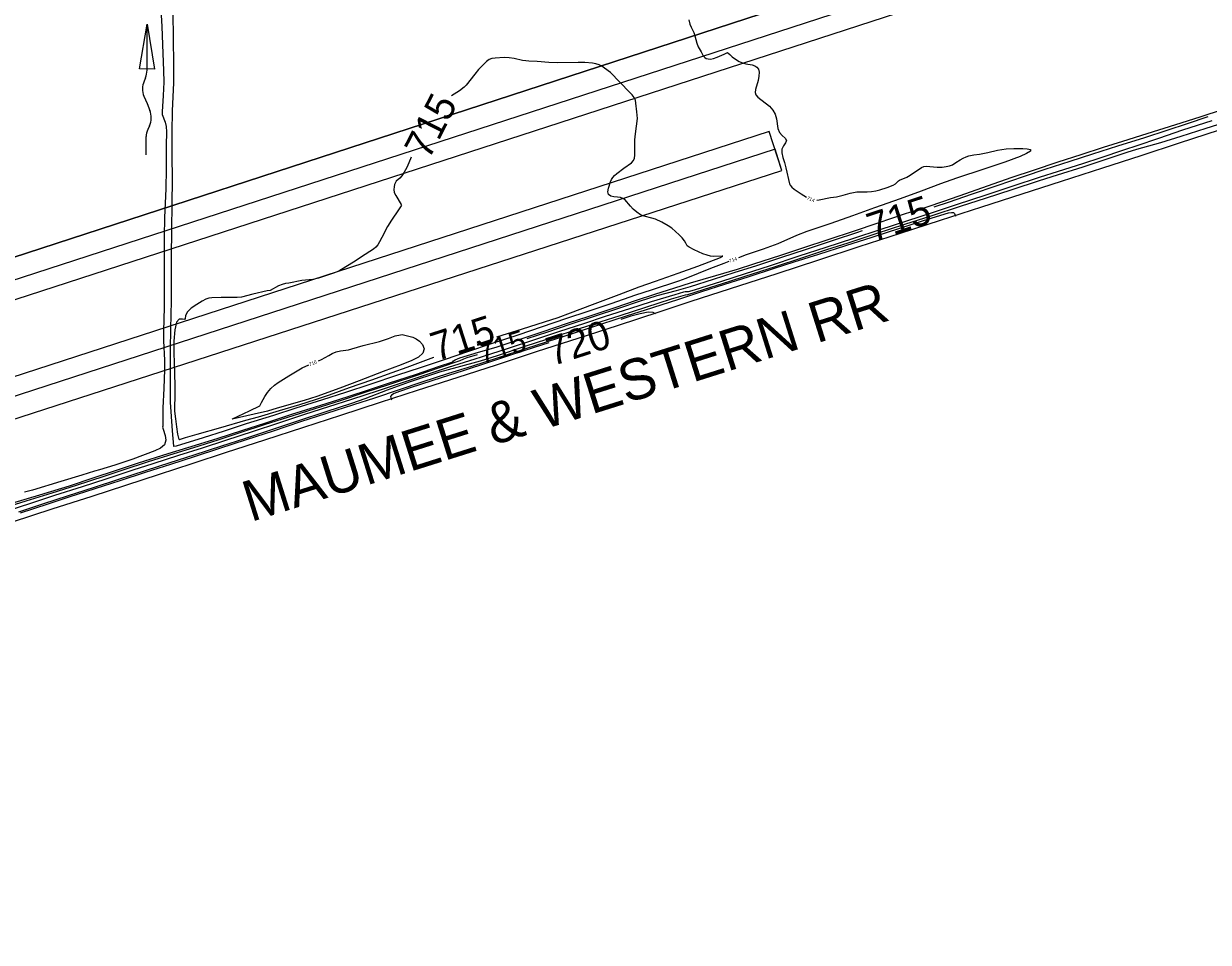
# Model space of a CAD drawing. Extents: x -468556195 to 3353078, y -306091294 to 1252632.
# Drawn here: x 1832292 to 1833652, y 533929 to 534984 of the extents above; entities that cross this region are included whole.
import ezdxf

# ---------------------------------------------------------------- set-up
doc = ezdxf.new("R2010")
doc.units = 0
for name, color, linetype in [('Default', 7, 'Continuous'), ('DT_X_Contour_Minor', 7, 'Continuous'), ('Level 14', 7, 'Continuous'), ('Level 19', 7, 'Continuous'), ('Level 31', 7, 'Continuous'), ('Level 40', 7, 'Continuous'), ('SC_Shading3', 7, 'Continuous')]:
    doc.layers.add(name, color=color, linetype=linetype)

msp = doc.modelspace()

# ---------------------------------------------------------------- linework, layer by layer
at = {"layer": 'Default'}
for points in [[(1827117.1, 533034.5), (1827123.3, 533015.5), (1834732.4, 535485.8), (1834724, 535511.6)], [(1827162.8, 532893.7), (1827168.8, 532875.3), (1833162.6, 534815.3), (1833154.9, 534839.7)]]:
    msp.add_lwpolyline(points, close=True, dxfattribs=at)
at = {"layer": 'DT_X_Contour_Minor'}
for points in [[(1833101.6, 534710.8), (1833095.9, 534708.6), (1833080.6, 534702.7), (1833052.3, 534691.2), (1833043.8, 534688.2), (1833012.6, 534677.9), (1832994.6, 534671.9), (1832966, 534662.2), (1832939.9, 534653.5), (1832915.1, 534645.1), (1832886.1, 534635.2), (1832860.4, 534626.7), (1832828.8, 534616.3), (1832801.4, 534607), (1832775.8, 534598.4), (1832747.2, 534588.7), (1832721.3, 534580.1), (1832689.2, 534569.5), (1832661.3, 534560.4), (1832635.1, 534551.9), (1832604.4, 534542.2), (1832578.6, 534534), (1832547.5, 534524.2), (1832522, 534516), (1832498.1, 534508.4), (1832466.8, 534498.8), (1832464.4, 534498.3), (1832464.2, 534498.9), (1832462.8, 534516.4), (1832460.5, 534549.3), (1832460.6, 534578.6), (1832460.4, 534602.3), (1832460.3, 534609.8), (1832460.9, 534633.5), (1832461.6, 534665.7), (1832461.7, 534691), (1832461.8, 534718.3), (1832461.9, 534744.6), (1832462.3, 534779.3), (1832462.6, 534802.6), (1832462.3, 534834.9), (1832462.3, 534859), (1832462.9, 534883.7), (1832464.1, 534915.7), (1832464.2, 534938.4), (1832464, 534965), (1832463.7, 534998.2)], [(1832449.8, 534993.3), (1832450.4, 534980.6), (1832451.6, 534949.3), (1832452.5, 534930.1), (1832452.8, 534916.4), (1832452.1, 534901.1), (1832450.9, 534882.6), (1832450.8, 534879.6), (1832454.5, 534870.5), (1832455.3, 534865.6), (1832455.7, 534859.5), (1832455.6, 534843.8), (1832455.4, 534817.2), (1832455.1, 534794.1), (1832453.7, 534761.2), (1832453.3, 534739), (1832453.2, 534712.3), (1832453.3, 534675.6), (1832453.2, 534658.4), (1832452.5, 534630.4), (1832452.5, 534619.7), (1832453.5, 534597.5), (1832453.6, 534586.7), (1832452.9, 534565), (1832451.8, 534542.8), (1832451.5, 534521.7), (1832451.3, 534520.4), (1832452, 534518.3), (1832454.4, 534511), (1832455.1, 534505.6), (1832453.6, 534500.4), (1832449, 534496.3), (1832442.5, 534493.2), (1832417.3, 534483.8), (1832396.5, 534476.8), (1832379.1, 534471.4), (1832373, 534469.9), (1832358.6, 534465.5), (1832334.6, 534458), (1832301.8, 534448.3), (1832292.9, 534445.8)], [(1833055.7, 534988), (1833056.8, 534983.3), (1833058.4, 534979.7), (1833061.6, 534973.6), (1833062.8, 534969.8), (1833065.1, 534961.2), (1833066.6, 534957.3), (1833069.8, 534951.3), (1833072.3, 534946.9), (1833074.3, 534944.7), (1833075.8, 534943.8), (1833077.9, 534943.2), (1833080.6, 534943), (1833084.2, 534943.7), (1833088.4, 534945.2), (1833096.3, 534948.8), (1833100.1, 534950.7), (1833100.6, 534950.3), (1833102.8, 534948.2), (1833105.6, 534945.7), (1833109.3, 534942.8), (1833113.4, 534940.3), (1833117.4, 534938.6), (1833121.2, 534937.7), (1833128.3, 534936.4), (1833131.5, 534935.4), (1833134, 534933.8), (1833135.7, 534931.4), (1833136.5, 534927.9), (1833136.3, 534923.6), (1833135.3, 534918.4), (1833132.5, 534908.3), (1833132, 534904.7), (1833132.7, 534902), (1833134.9, 534899.3), (1833148.3, 534889), (1833152.1, 534884.6), (1833154.8, 534879.7), (1833156.4, 534874.5), (1833158.1, 534863.5), (1833159.8, 534858.8), (1833162.9, 534855.2), (1833166.2, 534852.3), (1833167.8, 534849.7), (1833166.9, 534846.8), (1833164.5, 534843.6), (1833162.5, 534839.8), (1833162.4, 534835.3), (1833163.7, 534830.1), (1833165.5, 534824.4), (1833167.1, 534818.4), (1833171.2, 534800), (1833172.3, 534798.2), (1833174.1, 534796.2), (1833176.8, 534793.9), (1833184.9, 534788.3), (1833191, 534784.6)], [(1832835.2, 534624.1), (1832864.7, 534633.3), (1832889.8, 534641.3), (1832905.6, 534646.4), (1832920, 534651.6), (1832945.1, 534661.5), (1832975.6, 534672.9), (1832998.8, 534681.8), (1833017.4, 534688.2), (1833043.6, 534697.2), (1833065.9, 534705.3), (1833092.2, 534715.4), (1833094.7, 534716.7), (1833094.1, 534717), (1833084.2, 534716.3), (1833080.7, 534716.7), (1833076.7, 534717.8), (1833071.8, 534719.7), (1833061.9, 534724.2), (1833056.1, 534727.2), (1833053.7, 534728.7), (1833052.2, 534731.9), (1833050.7, 534734.5), (1833048.2, 534737.8), (1833044.7, 534741.5), (1833040.5, 534745.3), (1833036.2, 534748.8), (1833032.2, 534751.6), (1833024.9, 534755.8), (1833017.4, 534759.3), (1833013.3, 534760.6), (1833004.6, 534762.7), (1833000.2, 534764.4), (1832995.9, 534767.3), (1832991.9, 534770.7), (1832988.6, 534774.2), (1832982.1, 534781.7), (1832979.9, 534783.2), (1832977.2, 534784.1), (1832973.8, 534784.7), (1832969.8, 534785.1), (1832966, 534785.8), (1832963.4, 534787.6), (1832962.7, 534790.8), (1832963.4, 534794.8), (1832965.8, 534802.1), (1832967, 534804.8), (1832968.5, 534807.2), (1832970.4, 534809.4), (1832973.1, 534811.8), (1832981.2, 534817.7), (1832989.9, 534824), (1832992.3, 534826.7), (1832993.5, 534829.4), (1832993.8, 534832.9), (1832993.8, 534850.4), (1832994.4, 534857.3), (1832996.8, 534874.7), (1832996.1, 534882.4), (1832995, 534892.4), (1832994.4, 534895.9), (1832993.1, 534898.8), (1832990.7, 534901.9), (1832973.8, 534919.1), (1832968.6, 534925), (1832965.6, 534927.8), (1832958.9, 534932.8), (1832955.7, 534934.8), (1832952.6, 534936.3), (1832949, 534937.5), (1832945, 534938.3), (1832936.3, 534939.1), (1832928.6, 534939.1), (1832904.5, 534938.8), (1832894.8, 534939.3), (1832881.7, 534940.3), (1832871.9, 534940.6), (1832868.6, 534940.9), (1832864.7, 534941.6), (1832855.1, 534943.8), (1832849.5, 534944.6), (1832843.6, 534944.8), (1832833.2, 534944.1), (1832829.6, 534943.6), (1832826.6, 534942.5), (1832823.3, 534940.2), (1832819, 534936.2), (1832814.3, 534931.1), (1832809.8, 534925.8), (1832800.2, 534913.3), (1832797.7, 534910.7), (1832792.2, 534906.8), (1832783.1, 534900.8)], [(1832278.2, 534433.3), (1832310.3, 534442.8), (1832344.4, 534453.3), (1832372.9, 534462.7), (1832397.3, 534470.8), (1832423.7, 534479.5), (1832457.7, 534490.2), (1832480.5, 534497.2), (1832514.1, 534507.7), (1832543.4, 534517.2), (1832568.7, 534525.3), (1832599.9, 534535.3), (1832626.8, 534543.7), (1832652.6, 534551.9), (1832684.5, 534562.4), (1832710.9, 534571), (1832742.9, 534581.5), (1832768.2, 534590), (1832784.6, 534595.7), (1832785.4, 534596.7), (1832787.4, 534597.9), (1832792.8, 534600), (1832814.3, 534606.6), (1832834.5, 534612.5), (1832861.9, 534621.5), (1832887.3, 534629.9), (1832916.5, 534639.9), (1832941.1, 534648.1), (1832971.1, 534658), (1832995.8, 534666.3), (1833016.8, 534673.2), (1833039.6, 534680.6), (1833057.8, 534686.3), (1833086.9, 534694.6), (1833111.6, 534701.9), (1833130.4, 534707.9), (1833161.3, 534718.1), (1833186.6, 534726.3), (1833217.1, 534736.2), (1833244.8, 534745.6), (1833273, 534755.2), (1833304.6, 534765.8), (1833329.3, 534773.6), (1833348.6, 534779.8), (1833373.7, 534788.9), (1833398.7, 534797.7), (1833427.2, 534807.5), (1833451.6, 534815.7), (1833479.9, 534825.1), (1833506.2, 534833.7), (1833532, 534842), (1833554.1, 534848.8), (1833582, 534857.5), (1833615.1, 534868), (1833642.8, 534876.9), (1833669.9, 534885.6)], [(1833656.4, 534872.3), (1833622.6, 534861.4), (1833595, 534851.8), (1833570.4, 534843.6), (1833556.1, 534838.9), (1833527.7, 534829.3), (1833508.9, 534823.2), (1833478.6, 534813.8), (1833459.3, 534807.5), (1833426.8, 534796.8), (1833396.8, 534787), (1833362.9, 534775.9), (1833335.1, 534766.6), (1833305.6, 534757), (1833275.2, 534747.1), (1833244.9, 534737.1), (1833213.1, 534726.8), (1833182, 534716.7), (1833148.1, 534705.4), (1833120.5, 534696.5), (1833093.3, 534687.8), (1833061.9, 534677.9), (1833055.1, 534675.9), (1833052.7, 534675.8), (1833051.5, 534675.8), (1833049.5, 534675.4), (1833039.8, 534672.6), (1833012.4, 534664.4), (1832987.6, 534656.4), (1832959.8, 534647.4), (1832934.7, 534639.2), (1832907.4, 534630.2), (1832877.5, 534620.5), (1832849.4, 534611.4), (1832817.1, 534601), (1832809.8, 534598.5), (1832779.3, 534588.9), (1832758.7, 534582.2), (1832728.7, 534572.2), (1832699, 534562.4), (1832668.4, 534552.2), (1832641.9, 534543.9), (1832614.2, 534535.1), (1832583.4, 534524.9), (1832555.5, 534515.7), (1832523.7, 534505.3), (1832496.8, 534496.5), (1832469.8, 534487.9), (1832440.2, 534478.4), (1832417.1, 534471), (1832386.2, 534461), (1832359, 534452.1), (1832327.4, 534442), (1832299.7, 534432.9), (1832272.4, 534424.1)], [(1833337.4, 534773.3), (1833355, 534779.1), (1833380.3, 534788.1), (1833409.7, 534798), (1833441.3, 534808.7), (1833464.9, 534816.6), (1833493.6, 534825.8), (1833519.6, 534834.2), (1833548.6, 534843.6), (1833579.3, 534853.2), (1833605.2, 534861.6), (1833628.4, 534869.3), (1833652.3, 534877)], [(1832286.3, 534423.4), (1832314.9, 534432.9), (1832342, 534441.8), (1832373.1, 534451.8), (1832400, 534460.5), (1832432.8, 534471.1), (1832460.1, 534479.9), (1832487.8, 534488.8), (1832519.3, 534499), (1832545.9, 534507.7), (1832577.8, 534518.3), (1832606.6, 534527.8), (1832639.2, 534538.4), (1832668.9, 534548.1), (1832683.9, 534553.5), (1832709.8, 534563.4), (1832735.1, 534572.4), (1832769.9, 534584), (1832789.7, 534589.5), (1832816.4, 534596.8), (1832836, 534602.8), (1832867.8, 534613.4), (1832892.6, 534621.5), (1832920.9, 534630.6), (1832947.6, 534639.4), (1832976.8, 534648.9), (1833006.2, 534658.3), (1833035.9, 534667.7), (1833052.1, 534672.6), (1833054.7, 534672.9), (1833072.5, 534678.5), (1833103, 534688.2), (1833120.3, 534693.7), (1833155.4, 534705.1), (1833185.6, 534715.1), (1833214.1, 534724.5), (1833238.6, 534732.3), (1833270.8, 534742.7), (1833303.9, 534753.5), (1833333.9, 534763.3), (1833368.7, 534774.7), (1833396.5, 534783.5), (1833427.1, 534793.4), (1833458.5, 534803.7), (1833479.2, 534810.3), (1833508.7, 534819.5), (1833529.4, 534826.1), (1833559.2, 534836.2), (1833570.1, 534839.6), (1833597.8, 534847.3), (1833621.2, 534854.7), (1833649.7, 534863.7), (1833670.5, 534870.1)], [(1833202.6, 534781.2), (1833205.5, 534781.4), (1833218.6, 534784), (1833225.4, 534784.9), (1833232.8, 534787), (1833241.1, 534789.3), (1833248.5, 534790.6), (1833253.5, 534790.8), (1833260.5, 534790.8), (1833265.4, 534791.1), (1833270.4, 534791.8), (1833275.1, 534792.9), (1833283.6, 534795.7), (1833290.5, 534798.5), (1833293, 534799.9), (1833295.7, 534802.4), (1833296.5, 534803.3), (1833297.6, 534804), (1833306, 534807.6), (1833309.8, 534809.8), (1833322.9, 534818.5), (1833325.7, 534819.8), (1833328.2, 534820.1), (1833341.1, 534819), (1833346.6, 534819), (1833351.4, 534819.6), (1833355.3, 534820.7), (1833358.4, 534821.8), (1833362.4, 534824.2), (1833367.5, 534827.4), (1833370.9, 534829.3), (1833374.4, 534830.9), (1833377.5, 534831.9), (1833383.2, 534833), (1833389.5, 534833.9), (1833399, 534836), (1833410.4, 534838.5), (1833420, 534839.9), (1833429.1, 534840.4), (1833439.2, 534840.4), (1833444.4, 534840), (1833448, 534839.1), (1833448.1, 534837.3), (1833443.5, 534834.5), (1833436.1, 534831.2), (1833418.5, 534824.6), (1833394.7, 534816.6), (1833363.3, 534806.2), (1833344.6, 534799.8), (1833322.6, 534791.4), (1833298.6, 534782.5), (1833269, 534772.2), (1833243.7, 534763.1), (1833219, 534754.3), (1833191.1, 534745), (1833179.5, 534740.7), (1833157.8, 534731.1), (1833141.1, 534725), (1833121.4, 534718.2), (1833112.8, 534715)], [(1832736.7, 534830.4), (1832734.2, 534823.8), (1832731.7, 534818.5), (1832728.8, 534813.3), (1832726, 534809.1), (1832723.8, 534806.5), (1832719.6, 534802.9), (1832718.7, 534801.3), (1832717.9, 534799.2), (1832717.2, 534796.6), (1832716.9, 534793.5), (1832717.5, 534790), (1832719.2, 534786.3), (1832725.5, 534776.2), (1832725.7, 534775.3), (1832725.5, 534774.5), (1832722.4, 534769.9), (1832714.2, 534758), (1832709.8, 534750.8), (1832703, 534738.1), (1832700.5, 534733.3), (1832698.4, 534729.7), (1832696.2, 534727.1), (1832693.5, 534724.9), (1832679.7, 534716.1), (1832672.7, 534711), (1832661.9, 534704.4), (1832653.6, 534699.8), (1832647.8, 534697.4), (1832630.6, 534691.7), (1832627.3, 534690.8), (1832623.9, 534690.2), (1832611.3, 534688.8), (1832596.4, 534685.9), (1832592.7, 534685.4), (1832588.7, 534684.4), (1832584.4, 534682.6), (1832574.8, 534677.6), (1832571.6, 534676.9), (1832555, 534673.1), (1832542, 534669.8), (1832537.2, 534669.4), (1832518.7, 534669.3), (1832508, 534669), (1832504.4, 534668.5), (1832501, 534667.4), (1832496.7, 534665.2), (1832490.6, 534661.5), (1832484.2, 534657.1), (1832479.5, 534652.4), (1832477.6, 534648.3), (1832477.2, 534645.3), (1832476.6, 534644.1), (1832474.1, 534644.6), (1832470.6, 534644.6), (1832467.3, 534641.1), (1832465.3, 534632.1), (1832464.4, 534619.4), (1832464.2, 534605.8), (1832464.9, 534583.1), (1832465.4, 534567.2), (1832465.3, 534555.5), (1832465.1, 534544.2), (1832465.2, 534539), (1832466.3, 534530), (1832467.5, 534520.9), (1832468.5, 534512.4), (1832469.6, 534508), (1832470.3, 534506.5), (1832470.9, 534506.5), (1832477.8, 534508.6), (1832490.9, 534512.7), (1832518.3, 534520.3), (1832547, 534528.6), (1832561.6, 534532.4), (1832585.7, 534539.7), (1832609.1, 534546.6), (1832627, 534552.2), (1832643, 534557.7), (1832666.1, 534566), (1832691.7, 534574.9), (1832715, 534583.2), (1832732.4, 534589.3), (1832762.9, 534600.9), (1832763, 534600.9)], [(1832288.3, 534422.1), (1832319.9, 534432.5), (1832344.2, 534440.4), (1832373.9, 534450), (1832402.6, 534459.4), (1832431.9, 534468.9), (1832460.8, 534478.2), (1832487.9, 534487), (1832517.1, 534496.5), (1832547.8, 534506.4), (1832578.6, 534516.5), (1832610, 534526.9), (1832640.1, 534536.7), (1832671, 534546.5), (1832695, 534554.4), (1832723.5, 534563.9), (1832749.5, 534572.5), (1832780, 534582.4), (1832806.4, 534590.6), (1832837.3, 534600.6), (1832868.6, 534610.8), (1832893.5, 534618.9), (1832924.4, 534628.9), (1832955.7, 534639), (1832984.3, 534648.3), (1833014.3, 534657.9), (1833044.1, 534667.5), (1833070.8, 534676.1), (1833097.1, 534684.6), (1833123.7, 534693.2), (1833154.2, 534702.9), (1833176.6, 534710.2), (1833205.2, 534719.3), (1833236, 534729.1), (1833266.3, 534738.8), (1833298.2, 534749), (1833325.4, 534757.7), (1833353.9, 534766.5), (1833357.5, 534767.1), (1833359.7, 534766.9), (1833360.8, 534765.9), (1833362.1, 534762.6)], [(1832870.2, 534622.2), (1832894, 534630), (1832919.6, 534638.7), (1832947.4, 534647.9), (1832976.6, 534657.5), (1832999.2, 534665), (1833019.5, 534671.5), (1833041.5, 534677.6), (1833057.6, 534682), (1833084, 534690.3), (1833107.8, 534697.9), (1833133.9, 534706.3), (1833161.5, 534715.4), (1833190.7, 534724.9), (1833223, 534735.4), (1833248.8, 534744.1), (1833255.3, 534746.3)], [(1833017.5, 534650.5), (1833017.5, 534650.5), (1833014.9, 534652.3), (1833009.2, 534652.6), (1832999.8, 534650.8), (1832989, 534647.8), (1832977.8, 534644.2)], [(1832630.3, 534596.6), (1832633.8, 534598.2), (1832642.2, 534602.8), (1832646.3, 534605.2), (1832650.8, 534607), (1832655.6, 534608.1), (1832664.9, 534609.4), (1832668.7, 534610.3), (1832681.8, 534614.4), (1832700.3, 534618.7), (1832710.8, 534622.4), (1832718.6, 534625.2), (1832724.5, 534626.7), (1832726.6, 534626.9), (1832729.7, 534626.3), (1832738.7, 534623.7), (1832742.6, 534622), (1832746.6, 534619.3), (1832750, 534615.3), (1832751.6, 534610.4), (1832750.2, 534605.5), (1832745.1, 534600.9), (1832737.8, 534597.1), (1832725.2, 534592), (1832704.7, 534584.3), (1832677.2, 534573.8), (1832655, 534565.5), (1832628.6, 534555.6), (1832613.9, 534551), (1832583.1, 534542.2), (1832571.9, 534539.1), (1832556.7, 534535.4), (1832531.1, 534529.6), (1832531.7, 534530), (1832551.3, 534539.4), (1832563.1, 534545.1), (1832564.8, 534548.9), (1832568.8, 534555.9), (1832571.9, 534560.4), (1832575.7, 534564.9), (1832579.8, 534568.7), (1832584.2, 534571.9), (1832596.3, 534579.3), (1832611.5, 534588.6), (1832619.2, 534592)], [(1832895.1, 534617.5), (1832878.2, 534612), (1832851, 534603.2), (1832825.7, 534594.9), (1832796.6, 534585.4), (1832771.2, 534577.2), (1832736.8, 534566.1), (1832723.3, 534561.5), (1832717.4, 534559.1), (1832714.2, 534557.3), (1832713.3, 534555.8), (1832713.6, 534554.2), (1832714.3, 534552.3), (1832714.5, 534552.1)], [(1832263.8, 534426.5), (1832294.7, 534435.9), (1832324.7, 534445.2), (1832352.4, 534453.9), (1832384.2, 534464.4), (1832406, 534471.5), (1832435.1, 534481), (1832464.5, 534490.2), (1832487.4, 534497.4), (1832515.2, 534506.2), (1832540.6, 534514.5), (1832569.6, 534523.9), (1832601.4, 534534.1), (1832626.6, 534542.1), (1832655.7, 534551.3), (1832683, 534560.2), (1832712.4, 534569.9), (1832745, 534580.7), (1832769.4, 534588.9), (1832793.3, 534596.9), (1832797.3, 534598.9), (1832801.3, 534600.5), (1832813, 534604)]]:
    msp.add_lwpolyline(points, dxfattribs=at)
at = {"layer": 'Level 14'}
for points in [[(1833665, 534861.6), (1833618.7, 534846.6), (1833574.7, 534832.1), (1833530.7, 534818), (1833483.3, 534802.6), (1833438.1, 534788.1), (1833391.8, 534773.1), (1833344.4, 534757.8), (1833298.5, 534743), (1833250.9, 534727.5), (1833204.6, 534712.3), (1833156.7, 534696.7), (1833114.1, 534682.9), (1833058.1, 534664.7), (1833022.3, 534652.8), (1832973.5, 534637)], [(1832973.5, 534637), (1832928.1, 534622.2), (1832881.6, 534607.3), (1832834.5, 534591.9), (1832790.4, 534577.5), (1832743.7, 534562.5), (1832701.3, 534548.7), (1832655.7, 534533.9), (1832613.2, 534520.1), (1832568.6, 534505.5), (1832524.5, 534491.4), (1832484.8, 534478.4), (1832447.4, 534466.2), (1832408.6, 534453.7), (1832370.2, 534441.1), (1832324.1, 534426.3), (1832278.8, 534411.6)]]:
    msp.add_lwpolyline(points, dxfattribs=at)
at = {"layer": 'Level 31'}
for p, q in [((1832424.9, 534931.7), (1832433.8, 534983.2)), ((1832433.5, 534930.2), (1832433.8, 534983.2)), ((1832433.8, 534983.2), (1832442.1, 534931.6)), ((1832442.1, 534931.6), (1832424.9, 534931.7)), ((1832431.8, 534921.7), (1832430.1, 534917.6)), ((1832430, 534900.5), (1832433.5, 534891.9)), ((1832433.5, 534891.9), (1832436.6, 534884.2)), ((1832436.2, 534866.3), (1832434.3, 534862.1)), ((1832432.4, 534833.2), (1832432.5, 534854.1))]:
    msp.add_line(p, q, dxfattribs=at)
for centre, radius, start, end in [((1832411.1, 534930.4), 22.4, 337.3227, 359.6827), ((1832450.7, 534908.9), 22.4, 157.2839, 202.1277), ((1832415.9, 534875.7), 22.4, 335.15, 22.2585), ((1832451.7, 534854), 19.2, 155.1999, 179.6827)]:
    msp.add_arc(centre, radius, start, end, dxfattribs=at)
at = {"layer": 'SC_Shading3'}
for points in [[(1827130.1, 532994.6), (1827117.1, 533034.5), (1834724, 535511.6), (1834739.2, 535464.9)], [(1827156, 532914.7), (1827168.8, 532875.3), (1833162.6, 534815.3), (1833148.1, 534860)]]:
    msp.add_lwpolyline(points, close=True, dxfattribs=at)

# ---------------------------------------------------------------- texts
at = {"layer": 'Level 19'}
for s, height, rotation, p in [('715', 33, 62.8535, (1832757.1, 534826.4)), ('714', 4, 337.1914, (1833190.8, 534782.1)), ('715', 33, 18.2086, (1833267, 534733)), ('714', 4, 20.6322, (1833103, 534709.2)), ('715', 33, 17.7961, (1832765.7, 534596)), ('720', 33, 17.8706, (1832898.7, 534590.4)), ('715', 25, 18.1685, (1832818.3, 534592)), ('716', 4, 21.9844, (1832620.5, 534590.4))]:
    msp.add_text(s, height=height, rotation=rotation, dxfattribs=at).set_placement(p)
at = {"layer": 'Level 40'}
msp.add_text('MAUMEE & WESTERN RR', height=46.8, rotation=17.5171, dxfattribs=at).set_placement((1832552.6, 534411.5))

doc.saveas('drawing.dxf')
